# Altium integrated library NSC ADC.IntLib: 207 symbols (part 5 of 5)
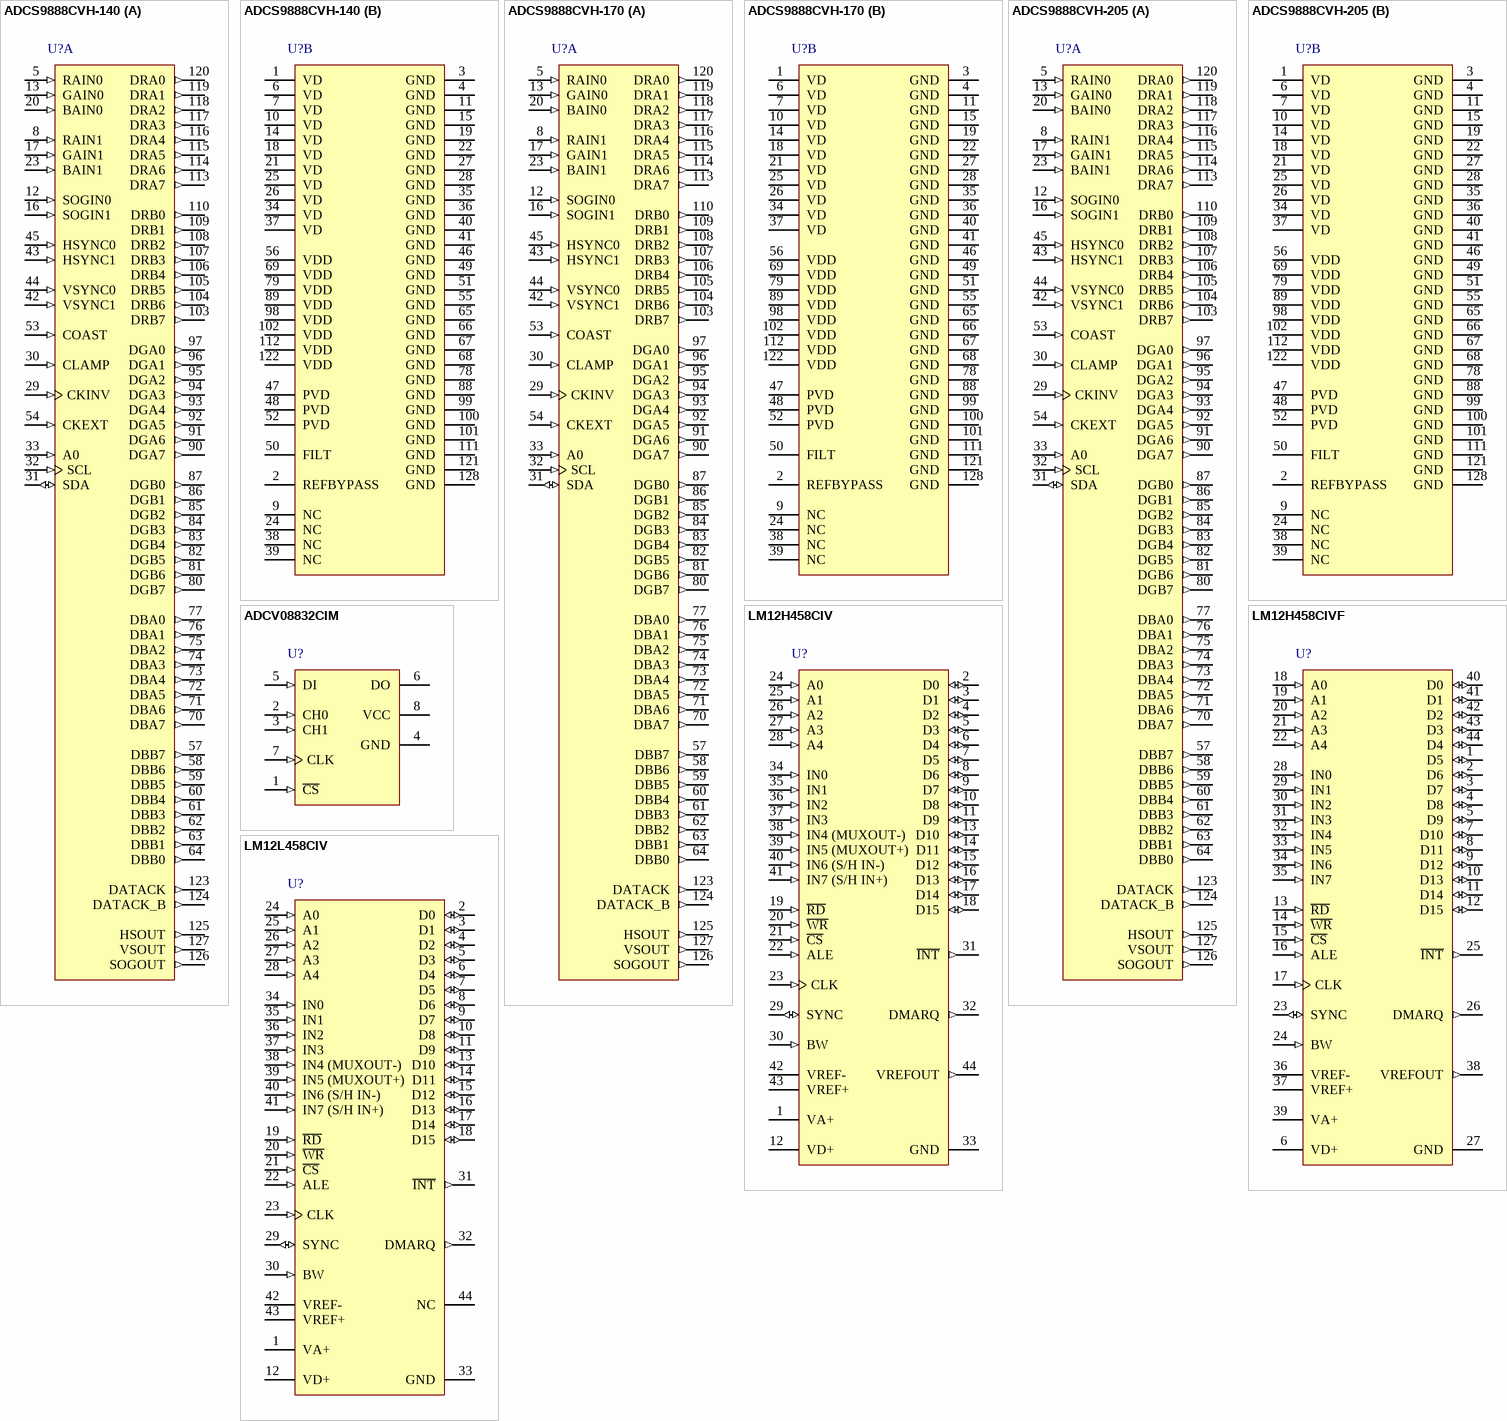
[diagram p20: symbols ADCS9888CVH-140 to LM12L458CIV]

## ADCS9888CVH-170
designator U?
205/170/140 MSPS Video Analog Front End; PartNumber: ADCS9888CVH-170; Manufacturer: National Semiconductor; CompType: ADC IC; PackageTopMarking: NSUZXYYTTE#*ADCS9888CVH*-170
footprint VLA128A_N (Shrink QFP, 128-Leads, Body 20x14 mm, Pitch 0.5mm, IPC Medium Density)
footprint VLA128A_L (Shrink QFP, 128-Leads, Body 20x14 mm, Pitch 0.5mm, IPC High Density)
footprint VLA128A_M (Shrink QFP, 128-Leads, Body 20x14 mm, Pitch 0.5mm, IPC Low Density)
part A pins: 5 RAIN0 (in), 8 RAIN1 (in), 12 SOGIN0 (in), 13 GAIN0 (in), 16 SOGIN1 (in), 17 GAIN1 (in), 20 BAIN0 (in), 23 BAIN1 (in), 29 CKINV (in), 30 CLAMP (in), 31 SDA (io), 32 SCL (in), 33 A0 (in), 42 VSYNC1 (in), 43 HSYNC1 (in), 44 VSYNC0 (in), 45 HSYNC0 (in), 53 COAST (in), 54 CKEXT (in), 57 DBB7 (out), 58 DBB6 (out), 59 DBB5 (out), 60 DBB4 (out), 61 DBB3 (out), 62 DBB2 (out), 63 DBB1 (out), 64 DBB0 (out), 70 DBA7 (out), 71 DBA6 (out), 72 DBA5 (out), 73 DBA4 (out), 74 DBA3 (out), 75 DBA2 (out), 76 DBA1 (out), 77 DBA0 (out), 80 DGB7 (out), 81 DGB6 (out), 82 DGB5 (out), 83 DGB4 (out), 84 DGB3 (out), 85 DGB2 (out), 86 DGB1 (out), 87 DGB0 (out), 90 DGA7 (out), 91 DGA6 (out), 92 DGA5 (out), 93 DGA4 (out), 94 DGA3 (out), 95 DGA2 (out), 96 DGA1 (out), 97 DGA0 (out), 103 DRB7 (out), 104 DRB6 (out), 105 DRB5 (out), 106 DRB4 (out), 107 DRB3 (out), 108 DRB2 (out), 109 DRB1 (out), 110 DRB0 (out), 113 DRA7 (out), 114 DRA6 (out), 115 DRA5 (out), 116 DRA4 (out), 117 DRA3 (out), 118 DRA2 (out), 119 DRA1 (out), 120 DRA0 (out), 123 DATACK (out), 124 DATACK_B (out), 125 HSOUT (out), 126 SOGOUT (out), 127 VSOUT (out)
part B pins: 1 VD (power), 2 REFBYPASS, 3 GND (power), 4 GND (power), 6 VD (power), 7 VD (power), 9 NC, 10 VD (power), 11 GND (power), 14 VD (power), 15 GND (power), 18 VD (power), 19 GND (power), 21 VD (power), 22 GND (power), 24 NC, 25 VD (power), 26 VD (power), 27 GND (power), 28 GND (power), 34 VD (power), 35 GND (power), 36 GND (power), 37 VD (power), 38 NC, 39 NC, 40 GND (power), 41 GND (power), 46 GND (power), 47 PVD (power), 48 PVD (power), 49 GND (power), 50 FILT, 51 GND (power), 52 PVD (power), 55 GND (power), 56 VDD (power), 65 GND (power), 66 GND (power), 67 GND (power), 68 GND (power), 69 VDD (power), 78 GND (power), 79 VDD (power), 88 GND (power), 89 VDD (power), 98 VDD (power), 99 GND (power), 100 GND (power), 101 GND (power), 102 VDD (power), 111 GND (power), 112 VDD (power), 121 GND (power), 122 VDD (power), 128 GND (power)

## ADCS9888CVH-205
designator U?
205/170/140 MSPS Video Analog Front End; PartNumber: ADCS9888CVH-205; Manufacturer: National Semiconductor; CompType: ADC IC; PackageTopMarking: NSUZXYYTTE#*ADCS9888CVH*-205
footprint VLA128A_N (Shrink QFP, 128-Leads, Body 20x14 mm, Pitch 0.5mm, IPC Medium Density)
footprint VLA128A_L (Shrink QFP, 128-Leads, Body 20x14 mm, Pitch 0.5mm, IPC High Density)
footprint VLA128A_M (Shrink QFP, 128-Leads, Body 20x14 mm, Pitch 0.5mm, IPC Low Density)
part A pins: 5 RAIN0 (in), 8 RAIN1 (in), 12 SOGIN0 (in), 13 GAIN0 (in), 16 SOGIN1 (in), 17 GAIN1 (in), 20 BAIN0 (in), 23 BAIN1 (in), 29 CKINV (in), 30 CLAMP (in), 31 SDA (io), 32 SCL (in), 33 A0 (in), 42 VSYNC1 (in), 43 HSYNC1 (in), 44 VSYNC0 (in), 45 HSYNC0 (in), 53 COAST (in), 54 CKEXT (in), 57 DBB7 (out), 58 DBB6 (out), 59 DBB5 (out), 60 DBB4 (out), 61 DBB3 (out), 62 DBB2 (out), 63 DBB1 (out), 64 DBB0 (out), 70 DBA7 (out), 71 DBA6 (out), 72 DBA5 (out), 73 DBA4 (out), 74 DBA3 (out), 75 DBA2 (out), 76 DBA1 (out), 77 DBA0 (out), 80 DGB7 (out), 81 DGB6 (out), 82 DGB5 (out), 83 DGB4 (out), 84 DGB3 (out), 85 DGB2 (out), 86 DGB1 (out), 87 DGB0 (out), 90 DGA7 (out), 91 DGA6 (out), 92 DGA5 (out), 93 DGA4 (out), 94 DGA3 (out), 95 DGA2 (out), 96 DGA1 (out), 97 DGA0 (out), 103 DRB7 (out), 104 DRB6 (out), 105 DRB5 (out), 106 DRB4 (out), 107 DRB3 (out), 108 DRB2 (out), 109 DRB1 (out), 110 DRB0 (out), 113 DRA7 (out), 114 DRA6 (out), 115 DRA5 (out), 116 DRA4 (out), 117 DRA3 (out), 118 DRA2 (out), 119 DRA1 (out), 120 DRA0 (out), 123 DATACK (out), 124 DATACK_B (out), 125 HSOUT (out), 126 SOGOUT (out), 127 VSOUT (out)
part B pins: 1 VD (power), 2 REFBYPASS, 3 GND (power), 4 GND (power), 6 VD (power), 7 VD (power), 9 NC, 10 VD (power), 11 GND (power), 14 VD (power), 15 GND (power), 18 VD (power), 19 GND (power), 21 VD (power), 22 GND (power), 24 NC, 25 VD (power), 26 VD (power), 27 GND (power), 28 GND (power), 34 VD (power), 35 GND (power), 36 GND (power), 37 VD (power), 38 NC, 39 NC, 40 GND (power), 41 GND (power), 46 GND (power), 47 PVD (power), 48 PVD (power), 49 GND (power), 50 FILT, 51 GND (power), 52 PVD (power), 55 GND (power), 56 VDD (power), 65 GND (power), 66 GND (power), 67 GND (power), 68 GND (power), 69 VDD (power), 78 GND (power), 79 VDD (power), 88 GND (power), 89 VDD (power), 98 VDD (power), 99 GND (power), 100 GND (power), 101 GND (power), 102 VDD (power), 111 GND (power), 112 VDD (power), 121 GND (power), 122 VDD (power), 128 GND (power)

## ADCV08832CIM
designator U?
Low Voltage, 8-Bit Serial I/O CMOS A/D Converter With Sample/Hold; PartNumber: ADCV08832CIM; Manufacturer: National Semiconductor; CompType: ADC IC; PackageTopMarking: NSZXTT*ADCV0*8832I
footprint M08A_N (SOIC, 8-Leads, Body 4.9x3.9mm, Pitch 1.27mm, IPC Medium Density)
footprint M08A_L (SOIC, 8-Leads, Body 4.9x3.9mm, Pitch 1.27mm, IPC High Density)
footprint M08A_M (SOIC, 8-Leads, Body 4.9x3.9mm, Pitch 1.27mm, IPC Low Density)
pins: 1 ~{CS} (in), 2 CH0 (in), 3 CH1 (in), 4 GND (power), 5 DI (in), 6 DO (hiz), 7 CLK (in), 8 VCC (power)

## LM12H458CIV
designator U?
12-Bit Plus Sign Data Acquisition System with Self-Calibration; PartNumber: LM12H458CIV; Manufacturer: National Semiconductor; CompType: ADC IC; PackageTopMarking: NSUZXYYTTE#*LM12H458CIV; PowerWise: N
footprint V44A_N (Leaded Chip Carrier, 44-Leads, Body 16.6x16.6mm, Pitch 1.27mm, IPC Medium Density)
footprint V44A_L (Leaded Chip Carrier, 44-Leads, Body 16.6x16.6mm, Pitch 1.27mm, IPC High Density)
footprint V44A_M (Leaded Chip Carrier, 44-Leads, Body 16.6x16.6mm, Pitch 1.27mm, IPC Low Density)
pins: 1 VA+ (power), 2 D0 (io), 3 D1 (io), 4 D2 (io), 5 D3 (io), 6 D4 (io), 7 D5 (io), 8 D6 (io), 9 D7 (io), 10 D8 (io), 11 D9 (io), 12 VD+ (power), 13 D10 (io), 14 D11 (io), 15 D12 (io), 16 D13 (io), 17 D14 (io), 18 D15 (io), 19 ~{RD} (in), 20 ~{WR} (in), 21 ~{CS} (in), 22 ALE (in), 23 CLK (in), 24 A0 (in), 25 A1 (in), 26 A2 (in), 27 A3 (in), 28 A4 (in), 29 SYNC (io), 30 BW (in), 31 ~{INT} (out), 32 DMARQ (out), 33 GND (power), 34 IN0 (in), 35 IN1 (in), 36 IN2 (in), 37 IN3 (in), 38 IN4 (MUXOUT-) (in), 39 IN5 (MUXOUT+) (in), 40 IN6 (S/H IN-) (in), 41 IN7 (S/H IN+) (in), 42 VREF- (power), 43 VREF+ (power), 44 VREFOUT (out)

## LM12H458CIVF
designator U?
12-Bit Plus Sign Data Acquisition System with Self-Calibration; PartNumber: LM12H458CIVF; Manufacturer: National Semiconductor; CompType: ADC IC; PackageTopMarking: NSUZXYYTT*LM12H458*CIVF*DIE RUN# =; PowerWise: N
footprint VGZ44A_N (QFP, 44-Leads, Body 10x10mm, Pitch 0.8mm, IPC Medium Density)
footprint VGZ44A_L (QFP, 44-Leads, Body 10x10mm, Pitch 0.8mm, IPC High Density)
footprint VGZ44A_M (QFP, 44-Leads, Body 10x10mm, Pitch 0.8mm, IPC Low Density)
pins: 1 D5 (io), 2 D6 (io), 3 D7 (io), 4 D8 (io), 5 D9 (io), 6 VD+ (power), 7 D10 (io), 8 D11 (io), 9 D12 (io), 10 D13 (io), 11 D14 (io), 12 D15 (io), 13 ~{RD} (in), 14 ~{WR} (in), 15 ~{CS} (in), 16 ALE (in), 17 CLK (in), 18 A0 (in), 19 A1 (in), 20 A2 (in), 21 A3 (in), 22 A4 (in), 23 SYNC (io), 24 BW (in), 25 ~{INT} (out), 26 DMARQ (out), 27 GND (power), 28 IN0 (in), 29 IN1 (in), 30 IN2 (in), 31 IN3 (in), 32 IN4 (in), 33 IN5 (in), 34 IN6 (in), 35 IN7 (in), 36 VREF- (power), 37 VREF+ (power), 38 VREFOUT (out), 39 VA+ (power), 40 D0 (io), 41 D1 (io), 42 D2 (io), 43 D3 (io), 44 D4 (io)

## LM12L458CIV
designator U?
12-Bit Plus Sign Data Acquisition System with Self-Calibration; PartNumber: LM12L458CIV; Manufacturer: National Semiconductor; CompType: ADC IC; PackageTopMarking: NSUZXYYTTE#*LM12L458CIV; PowerWise: N
footprint V44A_N (Leaded Chip Carrier, 44-Leads, Body 16.6x16.6mm, Pitch 1.27mm, IPC Medium Density)
footprint V44A_L (Leaded Chip Carrier, 44-Leads, Body 16.6x16.6mm, Pitch 1.27mm, IPC High Density)
footprint V44A_M (Leaded Chip Carrier, 44-Leads, Body 16.6x16.6mm, Pitch 1.27mm, IPC Low Density)
pins: 1 VA+ (power), 2 D0 (io), 3 D1 (io), 4 D2 (io), 5 D3 (io), 6 D4 (io), 7 D5 (io), 8 D6 (io), 9 D7 (io), 10 D8 (io), 11 D9 (io), 12 VD+ (power), 13 D10 (io), 14 D11 (io), 15 D12 (io), 16 D13 (io), 17 D14 (io), 18 D15 (io), 19 ~{RD} (in), 20 ~{WR} (in), 21 ~{CS} (in), 22 ALE (in), 23 CLK (in), 24 A0 (in), 25 A1 (in), 26 A2 (in), 27 A3 (in), 28 A4 (in), 29 SYNC (io), 30 BW (in), 31 ~{INT} (out), 32 DMARQ (out), 33 GND (power), 34 IN0 (in), 35 IN1 (in), 36 IN2 (in), 37 IN3 (in), 38 IN4 (MUXOUT-) (in), 39 IN5 (MUXOUT+) (in), 40 IN6 (S/H IN-) (in), 41 IN7 (S/H IN+) (in), 42 VREF- (power), 43 VREF+ (power), 44 NC

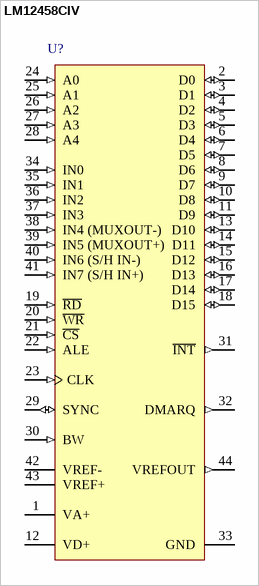
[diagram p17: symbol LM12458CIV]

## LM12458CIV
designator U?
12-Bit Plus Sign Data Acquisition System with Self-Calibration; PartNumber: LM12458CIV; Manufacturer: National Semiconductor; CompType: ADC IC; PackageTopMarking: NSUZXYYTTE#*LM12458CIV; PowerWise: N
footprint V44A_N (Leaded Chip Carrier, 44-Leads, Body 16.6x16.6mm, Pitch 1.27mm, IPC Medium Density)
footprint V44A_L (Leaded Chip Carrier, 44-Leads, Body 16.6x16.6mm, Pitch 1.27mm, IPC High Density)
footprint V44A_M (Leaded Chip Carrier, 44-Leads, Body 16.6x16.6mm, Pitch 1.27mm, IPC Low Density)
pins: 1 VA+ (power), 2 D0 (io), 3 D1 (io), 4 D2 (io), 5 D3 (io), 6 D4 (io), 7 D5 (io), 8 D6 (io), 9 D7 (io), 10 D8 (io), 11 D9 (io), 12 VD+ (power), 13 D10 (io), 14 D11 (io), 15 D12 (io), 16 D13 (io), 17 D14 (io), 18 D15 (io), 19 ~{RD} (in), 20 ~{WR} (in), 21 ~{CS} (in), 22 ALE (in), 23 CLK (in), 24 A0 (in), 25 A1 (in), 26 A2 (in), 27 A3 (in), 28 A4 (in), 29 SYNC (io), 30 BW (in), 31 ~{INT} (out), 32 DMARQ (out), 33 GND (power), 34 IN0 (in), 35 IN1 (in), 36 IN2 (in), 37 IN3 (in), 38 IN4 (MUXOUT-) (in), 39 IN5 (MUXOUT+) (in), 40 IN6 (S/H IN-) (in), 41 IN7 (S/H IN+) (in), 42 VREF- (power), 43 VREF+ (power), 44 VREFOUT (out)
